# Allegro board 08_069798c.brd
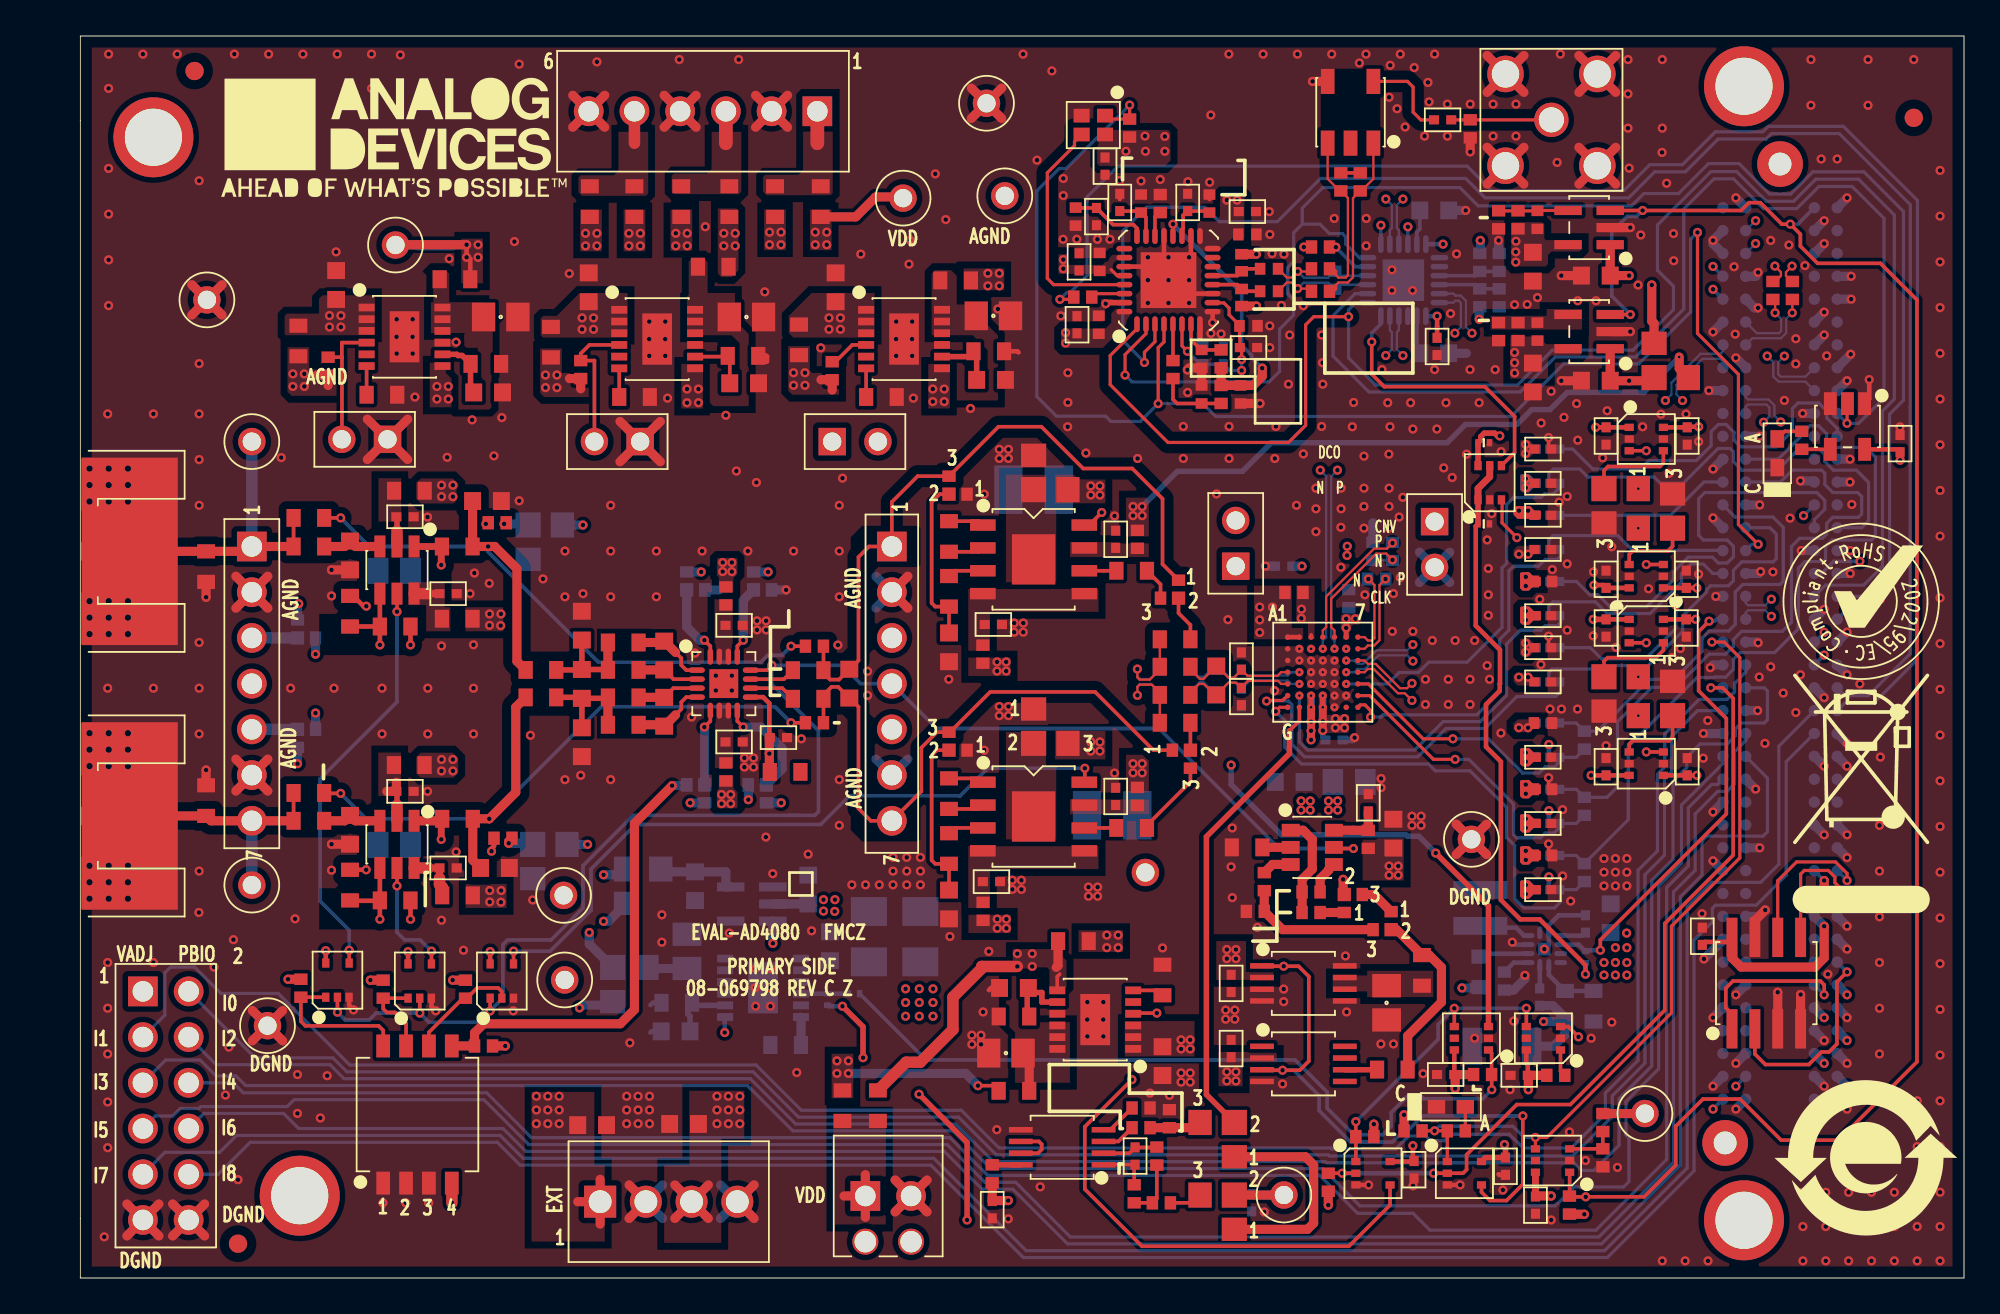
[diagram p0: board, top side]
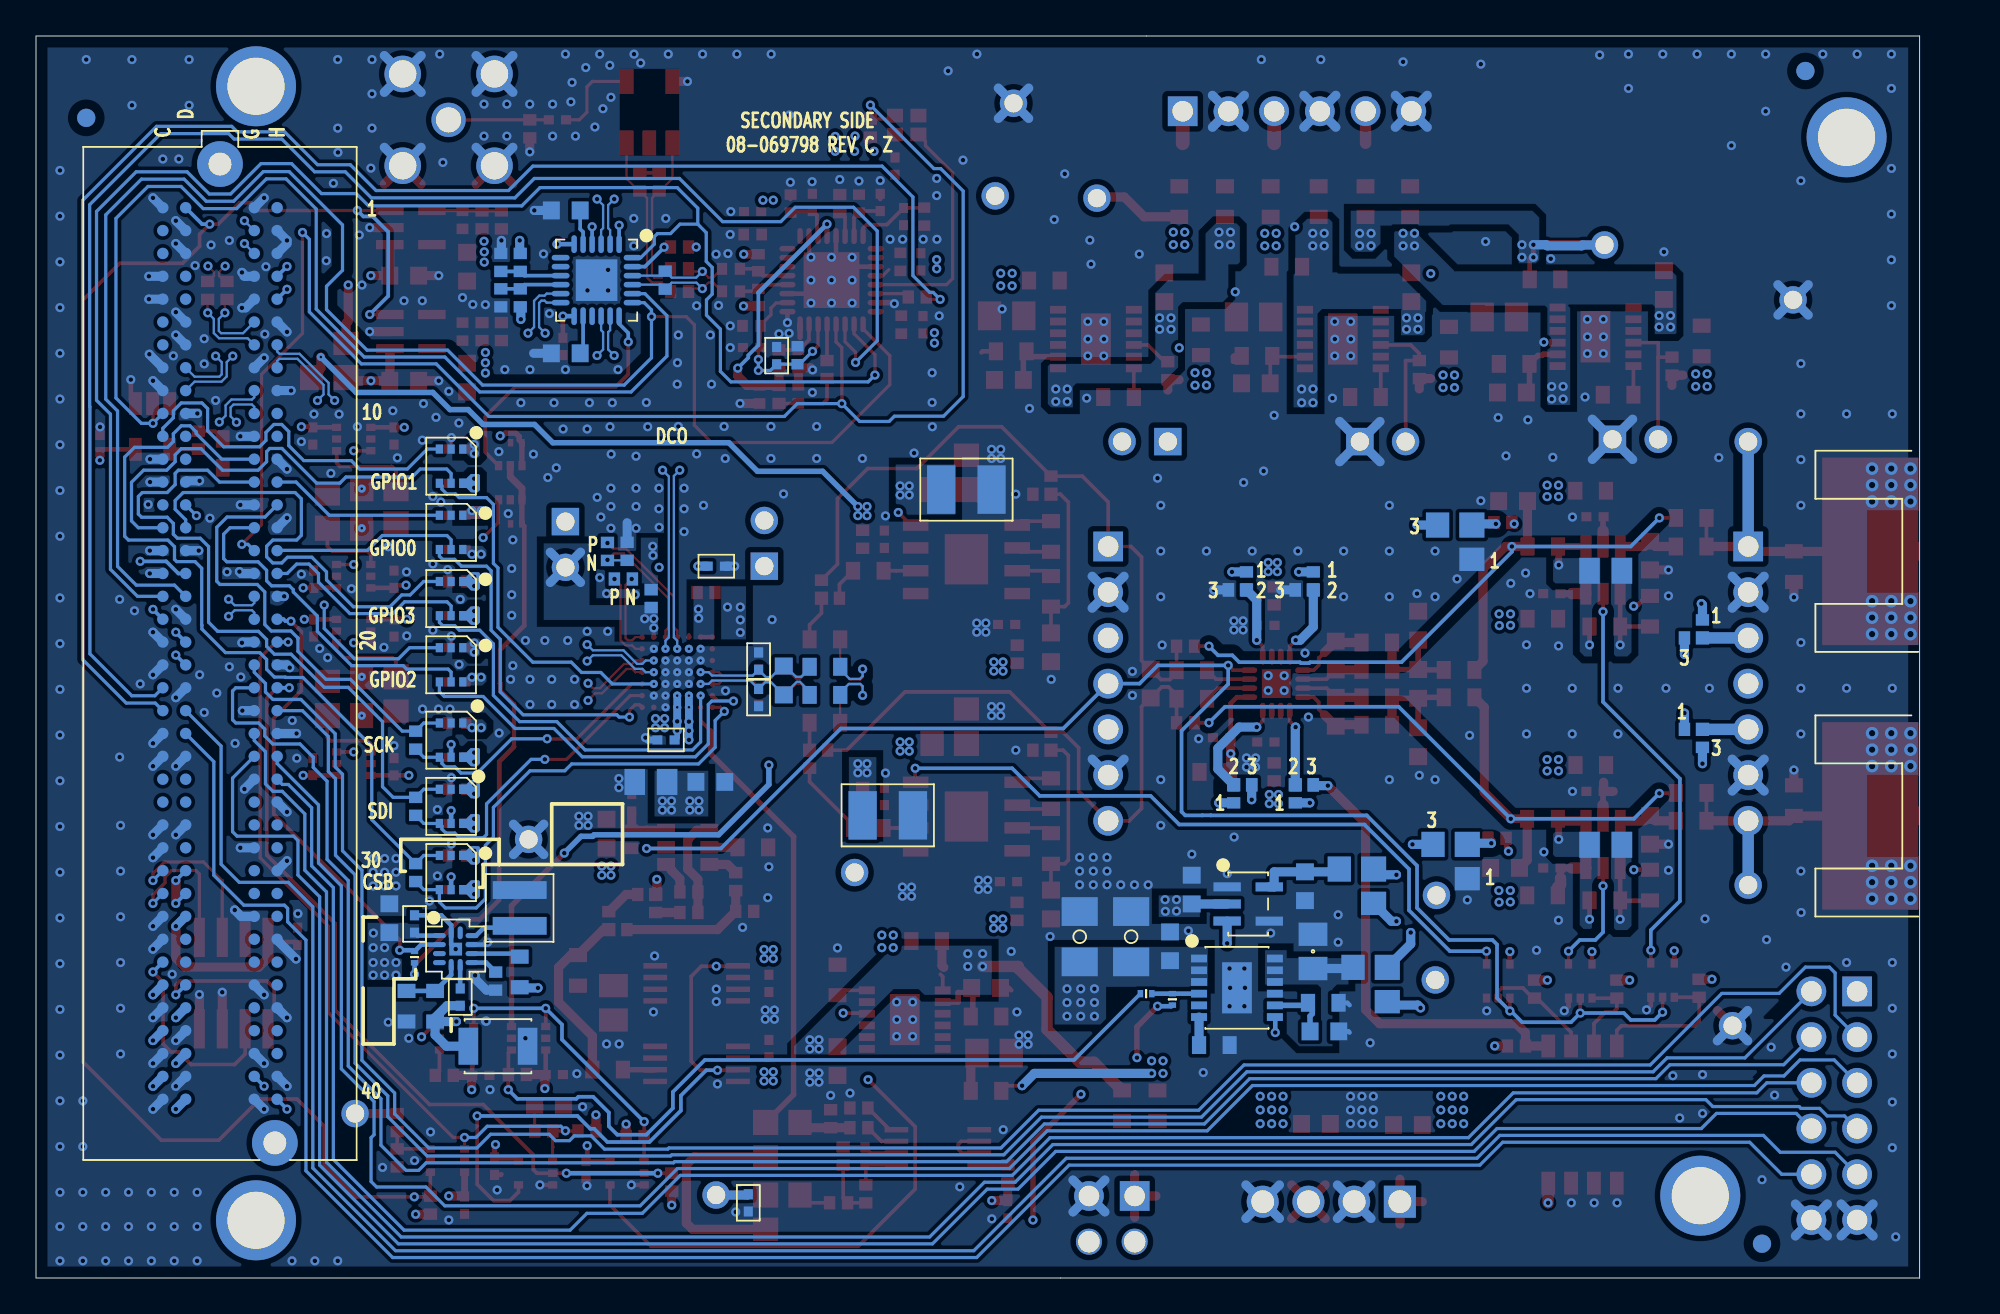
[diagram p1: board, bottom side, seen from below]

Outline 104.64 x 69 mm; copper layers: TOP, L2_GND, L3_PRIMARY_POWER, L4_GND, L5_SECONDARY_POWER, BOTTOM. Coordinates in mm from the lower left corner of the outline.
Outline path: 0,69 104.64,69 104.64,0 0,0 0,69

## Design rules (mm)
constraint set DEFAULT: min track width 0.203
net group CSB: nets CS_N_SRC CSB
net group DIFF_CLK_MATCH: nets CLK_N CLK_P
net group DP4: nets DOC_FMC DOD_FMC
net group DP5: nets DOA_FMC DOB_FMC
net group FDA_ON: nets UNNAMED_8_ADLT6236_I33_ VINP
net group FDA_OP: nets UNNAMED_8_ADLT6236_I15_ VINN
net group FPGACLK: nets FPGACLK_N FPGACLK_P
net group NEG_5V0: nets UNNAMED_12_ADLT8604_I100_FB UNNAMED_12_ADLT8604_I100_RT
net group OSC_EN: nets OSC_EN UNNAMED_7_ADP7118V2_I95_SENSE
net group PG_C2M: nets PG_C2M UNNAMED_12_LINLT3045_I87_EN
net group REFBUF_IN: nets REFBUF_IN UNNAMED_13_ADA48971_I40_
net group UNNAMED_4_CMOSNC7SZ125_I71_Y: nets UNNAMED_4_CMOSNC7SZ125_I71_Y UNNAMED_4_DIOLED_I76_P
net group UNNAMED_8_ADA4899_I108_INV: nets UNNAMED_8_ADA4899_I108_FEEDBACK UNNAMED_8_ADA4899_I108_INV
net group UNNAMED_8_ADA4899_I108_NINV: nets UNNAMED_8_ADA4899_I108_NINV UNNAMED_8_CAP_I93_N1
net group UNNAMED_8_ADA4899_I113_INV: nets UNNAMED_8_ADA4899_I113_FEEDBACK UNNAMED_8_ADA4899_I113_INV
net group UNNAMED_8_ADA4899_I113_NINV: nets UNNAMED_8_ADA4899_I113_NINV UNNAMED_8_CAP_I115_N1
net group UNNAMED_8_RES_I185_N2: nets UNNAMED_8_ADA4899_I108_VOUT UNNAMED_8_RES_I185_N2
net group UNNAMED_8_RES_I186_N2: nets UNNAMED_8_ADA4899_I113_VOUT UNNAMED_8_RES_I186_N2
net group UNNAMED_13_ADA48072_I13_NINV: nets UNNAMED_13_ADA48072_I13_NINV UNNAMED_13_RES_I12_N1
net group VOCM: nets UNNAMED_8_OFFPAGE_I160_A VOCM
net group 5V_SUPP: nets FDA5 PMSEL UNNAMED_8_ADA49451_I81__5 UNNAMED_13_ADA48072_I20_VS VDD_REFBUF VDDAFE_U1 VDDAFE_U2 VDDDRV_A1 VDDDRV_A6
net group +3V3VCCO: nets UNNAMED_7_ADP7118V2_I90_SENSE
net group ADF435X_LOCK: nets ADF435X_LOCK
net group AUXIN+: nets ADCIN+ AUXIN+ IN+ UNNAMED_8_RES_I163_N1
net group AUXIN-: nets ADCIN- AUXIN- IN- UNNAMED_8_RES_I164_N1
net group AVDD11: nets IOVDD
net group CLK_SRCM: nets UNNAMED_7_RES_I8_N1
net group CLK_SRCP: nets UNNAMED_7_RES_I10_N1
net group CNV_N: nets UNNAMED_4_CN160PCDGHV2_I97_LA00NCC
net group CNV_P: nets UNNAMED_4_CN160PCDGHV2_I97_LA00PCC
net group FDA8: nets FDA8
net group MATHCED_DIFFPAIR: nets DA_N DA_P DB_N DB_P DCO_N DCO_P
net group PWRGD: nets PWRGD
net group REF3P: nets REF3P REF3S UNNAMED_13_RES_I29_N2
net group REFBUF_OUT: nets REFBUF_OUT UNNAMED_13_ADA48971_I40__1 UNNAMED_13_ADA48971_I40_OUT
net group SCK: nets SCK
net group SDI: nets SDI
net group SNS33: nets UNNAMED_5_ADM108X_I19_VIN
net group UNNAMED_8_ADLT6236_I15__1: nets UNNAMED_8_ADLT6236_I15__1
net group UNNAMED_8_ADLT6236_I33__1: nets UNNAMED_8_ADLT6236_I33__1
net group UNNAMED_13_ADA48072_I13_INV: nets UNNAMED_13_ADA48072_I13_INV UNNAMED_13_ADA48072_I13_OUT UNNAMED_13_RES_I17_N2 UNNAMED_13_RES_I28_N2
net group VSSAFE: nets UNNAMED_8_ADA49451_I81__4 VSSAFE_U1 VSSAFE_U2 VSSDRV_A1 VSSDRV_A6
net group VTIN: nets CPO FFB UNNAMED_7_ADF435X_I58_SW VTIN

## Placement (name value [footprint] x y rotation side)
A1  ADA4899-1YRDZ  [SO8NB-3-PAD]  52.95 39.93 270 top
A2  ADM1085AKSZ  [SC70-6]  77.27 13.32 90 top
A3  ADM1085AKSZ  [SC70-6]  81.27 13.32 90 top
A4  ADM1085AKSZ  [SC70-6]  81.78 6.53 90 top
A5  ADA4807-2ARMZ  [MSOP8]  54.54 7.26 90 top
A6  ADA4899-1YRDZ  [SO8NB-3-PAD]  52.95 25.64 270 top
C1  0.1uF  [C0402H22]  89.26 46.78 270 top
C2  0.1uF  [C0201]  77.96 41.9 0 top
C3  0.1uF  [C0201]  77.96 46.4 0 top
C4  47uF  [C1206H71]  43.8 18.96 90 bottom
C5  47uF  [C1206H71]  46.66 18.96 90 bottom
C6  10uF  [C0603]  72.94 24.69 90 top
C7  TBD  [C0603_0805]  17.44 39.29 0 bottom
C8  TBD  [C0603_0805]  17.44 24.07 0 bottom
C9  0.1uF  [C0402H22]  71.55 26.4 90 top
C10  4.7uF  [C0603]  60.12 12.05 270 top
C11  4.7uF  [C0603]  28.24 55.04 90 top
C12  4.7uF  [C0603]  41.96 55.04 90 top
C13  4.7uF  [C0603]  14.21 55.17 90 top
C14  22uF  [C0805H60]  51.42 12.49 180 top
C15  56pF  [C0603]  27.86 36.24 270 top
C16  56pF  [C0603]  27.86 29.77 270 top
C17  82pF  [C0603]  32.44 34.58 90 top
C18  82pF  [C0603]  32.44 31.46 270 top
C19  0.1uF  [C0402H22]  36.32 36.26 0 top
C20  0.1uF  [C0402H22]  36.32 29.78 0 top
C21  22uF  [C0805H60]  37 53.39 0 top
C22  22uF  [C0805H60]  50.72 53.45 0 top
C23  22uF  [C0805H60]  23.35 53.39 0 top
C24  1uF  [C0603]  85.01 19.99 90 bottom
C25  4.7uF  [C0603]  41.64 18.43 90 bottom
C26  0.1uF  [C0402H22]  83.61 19.67 90 bottom
C27  0.1uF  [C0402H22]  81.07 15.61 270 bottom
C28  22uF  [C0805H60]  33.7 18.15 90 bottom
C29  22uF  [C1210H106]  78.98 12.88 0 bottom
C30  47uF  [C0805H60]  72.56 15.29 270 top
C31  8200pF  [C0603]  22.59 43.17 180 top
C32  8200pF  [C0603]  23.03 22.78 0 top
C33  0.1uF  [C0402H22]  38.78 30.02 0 top
C34  10uF  [C0603]  33.54 8.56 180 top
C35  27pF  [C0603]  63.1 33.2 90 top
C36  82pF  [C0402H22]  64.5 34.28 270 top
C37  82pF  [C0402H22]  64.5 32.31 270 top
C38  10pF  [C0603]  63.1 33.2 90 bottom
C39  82pF  [C0402H22]  64.5 34.28 270 bottom
C40  82pF  [C0402H22]  64.5 32.24 270 bottom
C41  TBD0805  [C0805]  70.48 27.56 0 bottom
C42  22uF  [C0603]  67.18 27.56 180 bottom
C43  0.1uF  [C0402H22]  69.64 29.89 0 bottom
C44  0.1uF  [C0402H22]  80.83 4.05 270 top
C45  0.01uF  [C0603]  50.59 49.9 0 top
C46  0.01uF  [C0603]  51.86 16.11 180 top
C47  0.1uF  [C0402H22]  75.85 11.3 180 top
C48  0.1uF  [C0402H22]  79.93 11.26 180 top
C49  10UF  [C0402]  81.25 23.47 0 top
C50  10UF  [C0402]  81.25 27.15 0 top
C51  10UF  [C0402]  81.25 30.83 0 top
C52  0.1uF  [C0402H22]  81.25 21.58 0 top
C53  0.1uF  [C0402H22]  81.25 25.25 0 top
C54  0.1uF  [C0402H22]  81.25 28.93 0 top
C55  0.1uF  [C0402H22]  79.17 6.21 270 top
C56  0.1uF  [C0402H22]  74.09 6.02 270 top
C57  0.1uF  [C0402H22]  63.93 12.75 90 top
C58  0.1uF  [C0402H22]  63.93 16.37 270 top
C59  0.1uF  [C0402H22]  89.21 36.11 270 top
C60  0.1uF  [C0402H22]  58.59 6.77 270 top
C61  0.1uF  [C0402H22]  50.66 3.8 270 top
C62  0.1uF  [C0402H22]  81.25 42.37 0 top
C63  0.1uF  [C0402H22]  101.09 46.36 90 top
C64  0.1uF  [C0402H22]  90.1 18.99 90 top
C65  0.1uF  [C0402H22]  75.67 64.34 180 top
C66  0.1uF  [C0402H22]  63.49 51.24 90 bottom
C67  15pF  [C0603]  14.98 40.14 270 top
C68  0.1uF  [C0402H22]  81.25 46.05 0 top
C69  0.47uF  [C0603]  75.21 51.37 0 bottom
C70  0.47uF  [C0603]  75.21 59.31 0 bottom
C71  0.1uF  [C0402H22]  81.25 35.02 0 top
C72  0.1uF  [C0402H22]  75.37 51.75 270 top
C73  10UF  [C0402]  81.25 38.69 0 top
C74  0.1uF  [C0402H22]  81.25 40.47 0 top
C75  1000PF  [C0603]  42.72 33.02 270 top
C76  0.1uF  [C0402H22]  81.25 44.15 0 top
C77  0.1uF  [C0402H22]  81.25 33.12 0 top
C78  0.1uF  [C0402H22]  81.25 36.79 0 top
C79  15pF  [C0603]  14.98 24.9 270 top
C80  0.1uF  [C0402H22]  84.75 36.11 270 top
C81  0.1uF  [C0402H22]  89.26 28.4 90 top
C82  0.1uF  [C0402H22]  84.75 46.78 270 top
C83  0.1uF  [C0402H22]  89.21 38.82 90 top
C84  0.1uF  [C0402H22]  84.75 28.4 90 top
C85  0.1uF  [C0402H22]  84.75 38.82 90 top
C86  0.01uF  [C0603]  36.88 49.71 0 top
C87  0.01uF  [C0603]  22.65 49.2 0 top
C88  0.1uF  [C0402H22]  20.43 38.02 0 top
C89  0.1uF  [C0402H22]  18.03 42.29 180 top
C90  0.1uF  [C0402H22]  20.43 22.78 0 top
C91  0.1uF  [C0402H22]  18.03 27.04 180 top
C92  22pF  [C0603]  48.25 20.75 270 top
C93  47uF  [C1210H95]  57.32 25.7 180 bottom
C94  47uF  [C1210H95]  52.95 43.8 0 bottom
C95  0.1uF  [C0402H22]  57.51 41.04 90 top
C96  0.1uF  [C0402H22]  50.72 36.31 180 top
C97  0.1uF  [C0402H22]  57.51 26.75 90 top
C98  0.1uF  [C0402H22]  50.61 22.02 180 top
C99  0.1uF  [C0402H22]  66.85 39.55 180 bottom
C100  0.1uF  [C0402H22]  65.07 4.18 90 bottom
C101  10uF  [C0603]  28.43 8.49 0 top
C102  0.01uF  [C0603]  33.07 13.7 180 bottom
C103  27PF  [C0603]  27.86 33.01 270 top
C104  1uF  [C0402]  80.94 58.79 270 top
C105  1uF  [C0402]  80.94 52.58 270 top
C109  22pF  [C0603]  48.25 35.04 270 top
C118  4.7uF  [C0603]  40.44 21.58 90 bottom
C119  4.7uF  [C0603]  34.15 21.77 270 bottom
C120  2000pF  [C0402]  64.45 49.09 270 top
C121  0.1uF  [C0402H22]  57.74 59.75 90 top
C122  0.027uF  [C0402]  62.29 49.09 90 top
C123  10pF  [C0402]  58.92 59.69 90 top
C124  0.1uF  [C0402H22]  55.37 52.96 90 top
C125  390pF  [C0402]  62.29 51.06 270 top
C126  10pF  [C0402]  64.89 52.9 0 top
C127  0.1uF  [C0402H22]  56.45 58.97 270 top
C128  0.1uF  [C0402H22]  64.89 51.69 0 top
C129  10pF  [C0402]  55.29 58.97 270 top
C130  10pF  [C0402]  56.57 52.96 90 top
C131  0.1uF  [C0402H22]  56.92 61.77 270 top
C132  10pF  [C0402]  62.34 51.27 90 bottom
C133  0.1uF  [C0402H22]  55.48 56.45 90 top
C134  10pF  [C0402]  56.62 56.45 90 top
C135  0.1uF  [C0402H22]  64.83 59.25 0 top
C136  0.1uF  [C0402H22]  61.51 59.75 90 top
C137  1000pF  [C0402]  66.03 54.82 0 top
C138  1000pF  [C0402]  66.03 56.07 0 top
C139  10pF  [C0402]  64.83 57.98 0 top
C140  10pF  [C0402]  62.72 59.69 90 top
C141  2.2uF  [C0603]  84.18 55.69 180 top
C142  2.2uF  [C0603]  84.18 49.85 180 top
C143  2.2uF  [C0603]  80.69 56.18 270 top
C144  2.2uF  [C0603]  80.69 50.02 270 top
CLKIN  1-1478979-0  [CNTYCO78974]  81.72 64.34 90 top
CNVEN  APT1608LVBC/D  [LED0603]  94.27 45.82 90 top
DS1  APT1608LZGCK  [LED0603]  76.14 9.51 0 top
INM  142-0701-851  [CNSMA10G62THK_EDGE]  0 25.67 180 top
INP  142-0701-851  [CNSMA10G62THK_EDGE]  0 40.37 180 top
IOVDD  RED  [CNKEY5001TP]  45.7 59.99 0 top
JP1  0  [3PINJUMPER_0402]  72.82 19.35 0 top
JP2  0  [3PINJUMPER_0402]  70.21 21.31 180 top
JP3  3PIN_JUMPER  [3PINJUMPER_0402]  33.68 38.23 180 bottom
JP4  3PIN_JUMPER  [3PINJUMPER_0402]  34.68 27.4 0 bottom
JP5  3PIN_JUMPER  [3PINJUMPER_0402]  37.4 38.23 180 bottom
JP6  3PIN_JUMPER  [3PINJUMPER_0402]  38.11 27.4 0 bottom
JP7  0  [3PINJUMPER_0603]  24.87 40.88 90 bottom
JP8  0  [3PINJUMPER_0603]  64.1 7.69 90 top
JP9  0  [3PINJUMPER_0603]  64.1 3.66 90 top
JP10  0  [3PINJUMPER_0603]  85.59 33.4 180 top
JP11  0  [3PINJUMPER_0603]  87.5 31.24 0 top
JP12  0  [3PINJUMPER_0603]  85.59 43.85 180 top
JP13  0  [3PINJUMPER_0603]  87.5 41.66 0 top
JP14  0  [3PINJUMPER_0603]  25.13 23.14 90 bottom
JP15  0  [3PINJUMPER_0402]  48.25 43.55 270 top
JP16  0  [3PINJUMPER_0402]  48.25 29.32 270 top
JP17  0  [3PINJUMPER_0402]  61.01 37.77 0 top
JP18  0  [3PINJUMPER_0402]  61.67 29.32 90 top
JP19  3PIN_JUMPER  [3PINJUMPER_0402]  12.06 35.56 180 bottom
JP20  3PIN_JUMPER  [3PINJUMPER_0402]  12.06 30.48 90 bottom
JP21  0  [3PINJUMPER_0603]  52.95 44.75 270 top
JP22  0  [3PINJUMPER_0603]  52.95 30.66 270 top
JP23  0  [3PINJUMPER_0603]  87.42 50.98 270 top
JP24  0  [3PINJUMPER_0603]  29.57 16.3 90 bottom
JP25  0  [3PINJUMPER_0603]  30.34 21.77 90 bottom
L1  47UH  [LSMSQ118H59_39X118]  77.77 20.56 90 bottom
L3  100nH  [L0402]  64.51 54.47 270 top
L4  100nH  [L0402]  64.51 56.4 90 top
NOREF  -  [unnamed]  8.76 1.91 0 top
NOREF#2  -  [unnamed]  6.34 67.06 0 top
NOREF#3  -  [unnamed]  92.42 3.2 0 top
NOREF#4  -  [#2]  42.6 -81.98 0 top
NOREF#5  -  [#2]  -130.37 -241.3 0 top
NOREF#6  -  [#2]  272.22 127.42 180 top
NOREF#7  -  [#2]  152.01 16.95 0 top
NOREF#8  -  [#2]  115.31 28.58 0 top
NOREF#9  -  [#2]  0.38 -9.14 270 top
NOREF#10  -  [#2]  99.18 6.68 0 top
NOREF#11  -  [#2]  0 0 0 top
NOREF#12  -  [#2]  0 69 0 top
NOREF#13  -  [#2]  104.64 0 0 top
NOREF#14  -  [#2]  33.95 -146.13 0 top
NOREF#15  -  [#2]  -4.32 1.02 0 top
NOREF#16  -  [unnamed]  101.85 64.45 0 top
NOREF#17  -  [#2]  0 69 0 top
NOREF#18  -  [unnamed]  92.42 66.21 0 top
NOREF#19  -  [#2]  -130.37 -241.3 0 top
NOREF#20  -  [#2]  -86.14 -57.15 0 top
NOREF#21  -  [#2]  3.47 3.22 0 top
NOREF#22  -  [#2]  71.61 31.16 0 top
NOREF#23  -  [#2]  -69.41 129.54 0 top
NOREF#24  -  [#2]  98.93 37.59 0 top
NOREF#25  -  [#2]  156.77 53.53 0 top
NOREF#26  -  [#2]  -130.37 -241.3 0 top
NOREF#27  -  [#2]  -9.32 39.65 0 top
NOREF#28  -  [#2]  3.47 3.22 0 top
NOREF#29  -  [unnamed]  12.19 4.57 0 top
NOREF#30  -  [#2]  104.64 0 90 top
NOREF#31  -  [#2]  10.73 2.9 0 top
NOREF#32  -  [#2]  17.44 63.89 0 top
NOREF#33  -  [unnamed]  4.06 63.37 0 top
NOREF#34  -  [#2]  108.2 37.16 0 top
NOREF#35  -  [#2]  -130.37 -241.3 0 top
NOREF#36  -  [#2]  60.45 149.19 0 top
NOREF#37  -  [#2]  0 0 0 top
NOREF#38  -  [unnamed]  101.85 64.45 180 bottom
NOREF#39  -  [unnamed]  6.34 67.06 180 bottom
NOREF#40  -  [unnamed]  8.76 1.91 180 bottom
P1  TSW-107-14-G-S  [CNTHMHDR1X7L700W100H433]  9.53 33.02 270 top
P2  SSW-107-01-T-S  [CNRCPT1X7H335LD35]  45.08 40.64 270 top
P3  ASP-134604-01  [CNSAMTECASP-134604-01]  94.42 34.7 270 bottom
P4  1725698  [CN1X6H335]  40.94 64.82 180 top
P5  69157-102HLF  [CNBERG69157-102]  17.06 46.59 180 top
P6  69157-102HLF  [CNBERG69157-102]  41.77 46.47 0 top
P7  TSW-106-07-F-D  [CNHDR2X6H330]  3.47 15.92 270 top
P8  1725672  [CNPHOENIX1725672]  28.87 4.24 0 top
P9  69157-102HLF  [CNBERG69157-102]  64.18 39.55 90 top
P10  69157-102HLF  [CNBERG69157-102]  75.23 42.02 270 top
P11  1725656  [CNTH1X2H335]  43.61 4.56 0 top
P12  69157-102HLF  [CNBERG69157-102]  31.1 46.47 180 top
R1  0  [R0402]  71.55 24.37 270 top
R2  49.9  [R0603]  6.98 39.52 270 top
R3  49.9  [R0603]  6.98 26.52 90 top
R4  0  [R0603]  12.69 40.64 0 top
R5  499  [R0603]  14.98 37.04 270 top
R6  0  [R0603]  12.69 25.4 0 top
R7  499  [R0603]  14.98 21.83 270 top
R8  499  [R0603]  17.49 36.2 0 top
R9  499  [R0603]  17.49 20.98 0 top
R10  300  [R0603]  25.59 33.78 0 top
R11  300  [R0603]  25.59 32.26 0 top
R12  0  [R0603]  30.16 33.78 0 top
R13  0  [R0603]  30.16 32.26 0 top
R14  300  [R0603]  30.16 35.31 0 top
R15  300  [R0603]  30.16 30.73 0 top
R16  10K  [R0402]  69.32 5.32 90 top
R17  0  [R0603]  48.25 41.2 90 top
R18  0  [R0402]  40.78 30.85 0 top
R19  100K  [R0402]  27.8 50.47 90 top
R20  100K  [R0402]  13.76 50.66 90 top
R21  0  [R0603]  35.16 56.18 0 top
R22  0  [R0603]  48.62 55.42 0 top
R23  0  [R0603]  20.81 55.48 0 top
R24  0  [R0201]  42.97 15.8 180 bottom
R26  0  [R0603]  18.28 43.74 0 top
R27  0  [R0603]  18.27 28.5 0 top
R28  0  [R0603]  20.95 21.26 0 top
R29  0  [R0402]  23.16 41.96 180 top
R30  0  [R0603]  39.15 28.12 0 top
R31  68  [R0603]  60.82 33.96 0 bottom
R32  20  [R0603]  60.82 33.96 0 top
R33  0  [R0402]  40.78 35.1 0 top
R34  0  [R0603]  44.31 9.57 90 top
R35  100K  [R0402]  41.77 50.4 90 top
R36  0  [R0402]  67.42 38.09 0 top
R37  0  [R0402]  70.47 37.74 270 bottom
R38  0  [R0402]  71.8 40.37 270 bottom
R39  0  [R0402]  94.03 54.86 270 top
R40  0  [R0402]  95.11 54.86 270 top
R41  35.7K  [R0402]  84.58 8.64 270 top
R42  10K  [R0402]  84.58 6.68 270 top
R43  10K  [R0402]  82.72 4.05 90 top
R44  10K  [R0402]  77.9 11.3 0 top
R45  10K  [R0402]  81.96 11.26 0 top
R46  1.5K  [R0402]  74.03 8.18 0 top
R47  10K  [R0402]  71.36 7.86 180 top
R48  10  [R0402]  58.92 8.35 180 top
R49  10  [R0402]  59.8 6.77 270 top
R50  0  [R0402]  58.54 4.68 270 top
R51  0  [R0402]  50.66 5.79 270 top
R52  0  [R0603]  12.69 42.23 0 top
R53  100K  [R0402]  12.25 16.1 270 top
R54  100K  [R0402]  22.4 12.89 0 top
R55  100K  [R0402]  16.82 16.05 270 top
R56  100K  [R0402]  21.39 16.05 270 top
R57  0  [R0603]  48.25 26.91 90 top
R58  25  [R0603]  48.25 38.15 90 top
R59  25  [R0603]  48.25 23.86 90 top
R60  1.1K  [R0402]  95.63 46.54 90 top
R61  100K  [R0402]  58.29 63.89 90 top
R62  100  [R0402]  77.21 63.84 270 top
R63  49.9  [R0402]  71.1 60.9 90 top
R64  49.9  [R0402]  70.02 60.9 270 top
R65  0  [R0402]  68.89 54.82 180 top
R66  0  [R0603]  20.94 40.64 0 top
R67  0  [R0402]  58.92 9.45 180 top
R68  0  [R0402]  68.89 56.07 180 top
R69  100  [R0402]  69.69 55.44 270 bottom
R70  0  [R0603]  60.82 35.48 180 top
R71  100K  [R0402]  68.89 57.28 0 top
R72  100K  [R0402]  77.74 56.42 270 bottom
R73  100K  [R0402]  78.82 56.42 90 bottom
R74  100K  [R0402]  77.74 54.45 90 bottom
R75  100K  [R0402]  78.82 54.45 270 bottom
R76  0  [R0603]  60.82 30.85 180 top
R77  100K  [R0201]  41.51 15.48 90 bottom
R78  0  [R0402]  23.48 24.43 0 top
R79  0  [R0603]  38.59 59.8 270 top
R80  0  [R0603]  33.38 59.8 270 top
R81  0  [R0603]  28.3 59.8 270 top
R82  0  [R0603]  42.34 9.57 90 top
R83  0  [R0603]  41.13 59.8 270 top
R84  0  [R0603]  36.05 59.8 270 top
R85  1.1K  [R0402]  76.44 8.18 0 top
R86  10K  [R0402]  60.5 8.85 90 top
R87  0  [R0402]  60.05 4.18 0 top
R88  20  [R0603]  60.82 32.4 0 top
R89  68  [R0603]  60.82 32.4 0 bottom
R90  0  [R0603]  30.78 59.8 270 top
R91  0  [R0603]  55.16 18.72 180 top
R92  0  [R0603]  26.14 51.99 90 top
R93  0  [R0603]  12.11 52.06 90 top
R94  0  [R0603]  39.92 52.12 90 top
R95  33K  [R0603]  51.86 14.53 180 top
R96  20K  [R0603]  36.81 51.23 0 top
R97  11K  [R0603]  50.46 51.48 0 top
R98  0  [R0402]  79.87 58.79 270 top
R99  10K  [R0402]  78.79 58.79 90 top
R100  0  [R0402]  79.87 52.58 270 top
R101  10K  [R0402]  78.79 52.58 90 top
R102  56  [R0603]  40.43 33.77 0 top
R103  56  [R0603]  40.43 32.18 0 top
R104  5.6  [R0603]  58.4 25 0 top
R105  5.6  [R0603]  58.4 39.29 0 top
R106  0  [R0603]  12.69 26.95 0 top
R107  11K  [R0603]  22.52 50.79 0 top
R108  3K  [R0603]  60.12 16.56 90 top
R109  0  [R0402]  83.55 22.52 270 bottom
R110  0  [R0402]  83.55 26.2 270 bottom
R111  0  [R0402]  83.55 29.88 270 bottom
R112  3K  [R0603]  30.79 48.94 0 top
R113  0  [R0603]  20.94 36.62 0 top
R114  0  [R0603]  20.95 25.51 0 top
R115  0  [R0402]  35.86 37.89 90 top
R116  0  [R0402]  35.86 28.12 270 top
R117  0  [R0402]  58.72 41.04 270 top
R118  0  [R0402]  58.72 26.75 270 top
R119  316  [R0402]  63.37 49.09 270 top
R120  845  [R0402]  63.37 51.06 90 top
R121  5.1K  [R0402]  59.99 59.69 90 top
R122  0  [R0402]  60.7 50.47 90 top
R123  0  [R0402]  55.68 54.5 180 top
R124  0  [R0402]  34.18 38.23 0 bottom
R125  0  [R0402]  34.18 27.4 180 bottom
R126  0  [R0402]  37.9 38.23 0 bottom
R127  0  [R0402]  37.61 27.4 180 bottom
R128  0  [R0402]  50.13 34.66 90 top
R129  0  [R0402]  50.15 20.37 90 top
R130  3K  [R0603]  44.5 48.94 0 top
R131  3K  [R0603]  16.75 49.07 0 top
R132  0  [R0603]  51.86 10.4 180 top
R133  100K  [R0201]  83.61 17.83 90 bottom
R134  50K  [R0603]  33.13 15.29 180 bottom
R135  500  [R0603]  39.18 12.94 180 bottom
R136  0  [R0402]  79.1 16.5 270 bottom
R137  18.2K  [R0603]  77.77 17 270 bottom
R138  187K  [R0603]  82.47 15.1 270 bottom
R139  1MEG  [R0603]  84.06 15.1 270 bottom
R146  0  [R0603]  72.88 11.58 0 top
R147  0  [R0603]  74.53 17.09 90 top
R148  10K  [R0402]  65.27 20.37 180 top
R149  0  [R0402]  65.77 22.02 90 top
R150  0  [R0402]  68.37 21.45 180 top
R151  0  [R0402]  68.37 20.31 0 top
R152  0  [R0603]  64.82 23.92 180 top
REF  RED  [CNKEY5001TP]  59.16 22.53 0 top
RTCLK  100  [R0402]  72.01 38.83 0 bottom
RTCNV  100  [R0402]  72.89 40.36 270 bottom
S1  218-4LPST  [SWSML246W228H104]  18.73 9.08 0 top
T1  MABA-007159-000000  [ETC1]  70.56 64.76 180 top
TINM  RED  [CNKEY5001TP]  9.53 21.83 0 top
TINP  RED  [CNKEY5001TP]  9.53 46.47 0 top
TP1  BLK  [CNKEY5001TP]  77.27 24.37 0 top
TP2  BLK  [CNKEY5001TP]  7.03 54.34 0 top
TP3  BLK  [CNKEY5001TP]  50.34 65.26 0 top
TP4  BLK  [CNKEY5001TP]  10.4 14.02 0 top
U1  LT6236HS6#TRMPBF  [TSOT23_6]  17.59 39.33 180 top
U2  LT6236HS6#TRMPBF  [TSOT23_6]  17.59 24.09 180 top
U3  ADA4945-1ACPZ-R7  [QFN16_3X3_PAD1_6X1_6]  35.75 33.02 270 top
U4  SN74AVC1T45DCKR  [SC70-6]  86.99 35.94 270 top
U5  SN74AVC1T45DCKR  [SC70-6]  86.99 28.58 90 top
U6  SN74AVC1T45DCKR  [SC70-6]  86.99 46.61 270 top
U7  SN74AVC1T45DCKR  [SC70-6]  86.99 38.99 90 top
U8  AD4080  [BGA49_5X5]  69.02 33.66 270 top
U9  SN74AVC1T45DCKR  [SC70-6]  78.29 44.18 0 top
U11  SN74AVC1T45DCKR  [SC70-6]  81.58 22.52 0 bottom
U12  SN74AVC1T45DCKR  [SC70-6]  81.58 26.2 0 bottom
U13  SN74AVC1T45DCKR  [SC70-6]  81.58 29.88 0 bottom
U14  SN74AVC1T45DCKR  [SC70-6]  81.58 41.42 0 bottom
U15  SN74AVC1T45DCKR  [SC70-6]  81.58 45.1 0 bottom
U16  SN74AVC1T45DCKR  [SC70-6]  81.58 34.07 0 bottom
U17  SN74AVC1T45DCKR  [SC70-6]  81.58 37.74 0 bottom
U18  M24C02-RMN6TP  [SO8]  93.66 16.38 0 top
U19  ADP7182AUJZ-2.5  [TSOT-5]  37.3 20.78 270 bottom
U20  AD9508BCPZ  [QFN24_4X4_PAD2_3X2_3]  73.5 55.44 0 bottom
U21  LT3045EMSE#PBF  [MSOP12_PAD2_845X1_651]  56.38 14.36 90 top
U23  TC7S08FU,LF  [SC70-5_A]  76.89 5.82 270 top
U24  TC7S08FU,LF  [SC70-5_A]  71.81 5.82 270 top
U25  LTC6655BHMS8-3#PBF  [MSOP8]  67.94 16.37 270 top
U26  SN74LVC1G00DCKT  [SC70-5]  14.28 16.55 0 top
U27  SN74LVC1G00DCKT  [SC70-5]  18.85 16.5 0 top
U28  TC7S08FU,LF  [SC70-5_A]  23.41 16.5 0 top
U29  NC7SZ125M5X  [SOT23-M12]  98.17 47.31 180 top
U30  ADF4350BCPZ  [QFN32_5X5_PAD3_1X3_1]  60.45 55.44 0 top
U31  ADP7118AUJZ-3.3  [TSOT-5]  83.81 58.36 90 top
U32  ADP7118AUJZ-3.3  [TSOT-5]  83.81 52.58 90 top
U33  LT3045EMSE#PBF  [MSOP12_PAD2_845X1_651]  32.04 52.16 270 top
U34  LT3045EMSE#PBF  [MSOP12_PAD2_845X1_651]  45.76 52.16 270 top
U35  LT3045EMSE#PBF  [MSOP12_PAD2_845X1_651]  18.01 52.29 270 top
U36  LT6657BHMS8-3#PBF  [MSOP8]  67.94 11.9 270 top
U37  LT3045EMSE#PBF  [MSOP12_PAD2_845X1_651]  37.92 16.12 270 bottom
U38  LT8604CAV#TRMPBF  [QFN12_2X2_PAD0_7X0_7]  81.33 18.27 270 bottom
U39  ADA4897-1ARJZ  [SOT23_6-2]  68.44 23.92 270 top
UNK5V_VDD  RED  [CNKEY5001TP]  26.84 21.26 0 top
VDD33  RED  [CNKEY5001TP]  86.91 9.14 0 top
VDD_11  RED  [CNKEY5001TP]  17.51 57.39 0 top
VDDLDO  RED  [CNKEY5001TP]  51.35 60.12 0 top
VOCM  RED  [CNKEY5001TP]  66.86 4.61 180 top
VSS2V5  RED  [CNKEY5001TP]  26.91 16.56 0 top
Y1  25MEGHZ  [YSML79W63H31_A]  56.27 64.05 180 top

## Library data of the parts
A1 A6 = ADA4899: Tolerance: N/A; User Part Number: UPN; alternate symbols: (SO8NB-3-PAD); part number: ADA4899_SM-ADA4899-1YRDZ,E005983,SO8NB-3-PAD; tolerance: N/A
A2-A4 = ADM108X: Tolerance: N/A; User Part Number: UPN; alternate symbols: (SC70-6); part number: ADM108X_SM-ADM1085AKSZ,E014794,SC70-6; tolerance: N/A
A5 = ADA4807_2: Tolerance: N/A; User Part Number: UPN; alternate symbols: (MSOP8); part number: ADA4807_2_SM-ADA4807-2ARMZ,E025561,MSOP8; tolerance: N/A
C1 C9 C19 C20 C26 C27 C33 C43 C44 C47 C48 C52-C66 C68 C71 C72 C74 C76-C78 C80-C85 C88-C91 C95-C100 C121 C124 C127 C128 C131 C133 C135 C136 = CAP: Tolerance: 10; User Part Number: UPN; alternate symbols: (C0402H22); part number: CAP_SM-0.1UF,50V,10,E018452,C0402H22; tolerance: 10
C2 C3 = CAP: Tolerance: 10; User Part Number: UPN; alternate symbols: (C0201); part number: CAP_SM-0.1UF,25V,10,E022721,C0201; tolerance: 10
C4 C5 = CAP: Tolerance: 20; User Part Number: UPN; alternate symbols: (C1206H71); part number: CAP_SM-47UF,16V,20,E033215,C1206H71; tolerance: 20
C6 C34 C101 = CAP: User Part Number: UPN; Tolerance: 10; alternate symbols: (C0603); part number: CAP_SM-10UF,25V,10,E030977,C0603; tolerance: 10
C7 C8 = CAP: User Part Number: UPN; Tolerance: N/A; alternate symbols: (C0603_0805); part number: CAP_SM-TBD,N/A,N/A,E029810,C0603_0805; tolerance: N/A
C10-C13 C25 = CAP: User Part Number: UPN; Tolerance: 10; alternate symbols: (C0603); part number: CAP_SM-4.7UF,16V,10,E020112,C0603; tolerance: 10
C14 C21-C23 C28 = CAP: Tolerance: 20; User Part Number: UPN; alternate symbols: (C0805H60); part number: CAP_SM-22UF,25V,20,E032575,C0805H60; tolerance: 20
C15 C16 = CAP: User Part Number: UPN; Tolerance: 5; alternate symbols: (C0603); part number: CAP_SM-56PF,50V,5,E000413,C0603; tolerance: 5
C17 C18 = CAP: User Part Number: UPN; Tolerance: 5; alternate symbols: (C0603); part number: CAP_SM-82PF,50V,5,E000414,C0603; tolerance: 5
C24 = CAP: User Part Number: UPN; Tolerance: 10; alternate symbols: (C0603); part number: CAP_SM-1UF,50V,10,E023087,C0603; tolerance: 10
C29 = CAP: Tolerance: 20; User Part Number: UPN; alternate symbols: (C1210H106); part number: CAP_SM-22UF,16V,20,E034214,C1210H106; tolerance: 20
C30 = CAP: Tolerance: 20; User Part Number: UPN; alternate symbols: (C0805H60); part number: CAP_SM-47UF,6.3V,20,E025498,C0805H60; tolerance: 20
C31 C32 = CAP: User Part Number: UPN; Tolerance: 5; alternate symbols: (C0603); part number: CAP_SM-8200PF,25V,5,E024853,C0603; tolerance: 5
C35 = CAP: User Part Number: UPN; Tolerance: 5; alternate symbols: (C0603); part number: CAP_SM-27PF,50V,5,E000395,C0603; tolerance: 5
C36 C37 C39 C40 = CAP: Tolerance: 5; User Part Number: UPN; alternate symbols: (C0402H22); part number: CAP_SM-82PF,50V,5,E026785,C0402H22; tolerance: 5
C38 = CAP: User Part Number: UPN; Tolerance: 0.5pF; alternate symbols: (C0603); part number: CAP_SM-10PF,50V,0.5PF,E016319,C0603; tolerance: 0.5pF
C41 = CAP: User Part Number: UPN; alternate symbols: (C0805); part number: CAP_SM-TBD0805,TBD0805,TBD0805,E000383,C0805
C42 = CAP: User Part Number: UPN; Tolerance: 20; alternate symbols: (C0603); part number: CAP_SM-22UF,6.3V,20,E021512,C0603; tolerance: 20
C45 C46 C86 C87 C102 = CAP: User Part Number: UPN; Tolerance: 10; alternate symbols: (C0603); part number: CAP_SM-0.01UF,200V,10,E031666,C0603; tolerance: 10
C49-C51 C73 = CAP: User Part Number: UPN; Tolerance: 20; alternate symbols: (C0402); part number: CAP_SM-10UF,10V,20,E061569,C0402; tolerance: 20
C67 C79 = CAP: User Part Number: UPN; Tolerance: 5; alternate symbols: (C0603); part number: CAP_SM-15PF,50V,5,E000409,C0603; tolerance: 5
C69 C70 = CAP: User Part Number: UPN; Tolerance: 10; alternate symbols: (C0603); part number: CAP_SM-0.47UF,16V,10,E012085,C0603; tolerance: 10
C75 = CAP: User Part Number: UPN; Tolerance: 1; alternate symbols: (C0603); part number: CAP_SM-1000PF,100V,1,E055828,C0603; tolerance: 1
C92 C109 = CAP: User Part Number: UPN; Tolerance: 5; alternate symbols: (C0603); part number: CAP_SM-22PF,50V,5,E000411,C0603; tolerance: 5
C93 C94 = CAP: Tolerance: 10; User Part Number: UPN; alternate symbols: (C1210H95); part number: CAP_SM-47UF,25V,10,E038014,C1210H95; tolerance: 10
C103 = CAP: User Part Number: UPN; Tolerance: 5; alternate symbols: (C0603); part number: CAP_SM-27PF,50V,5,E062032,C0603; tolerance: 5
C104 C105 = CAP: User Part Number: UPN; Tolerance: 10; alternate symbols: (C0402); part number: CAP_SM-1UF,16V,10,E019219,C0402; tolerance: 10
C118 C119 = CAP: User Part Number: UPN; Tolerance: 10; alternate symbols: (C0603); part number: CAP_SM-4.7UF,35V,10,E039350,C0603; tolerance: 10
C120 = CAP: User Part Number: UPN; Tolerance: 5; alternate symbols: (C0402); part number: CAP_SM-2000PF,25V,5,E019563,C0402; tolerance: 5
C122 = CAP: User Part Number: UPN; Tolerance: 5; alternate symbols: (C0402); part number: CAP_SM-0.027UF,16V,5,E021301,C0402; tolerance: 5
C123 C126 C129 C130 C132 C134 C139 C140 = CAP: User Part Number: UPN; Tolerance: 5; alternate symbols: (C0402); part number: CAP_SM-10PF,50V,5,E007982,C0402; tolerance: 5
C125 = CAP: User Part Number: UPN; Tolerance: 5; alternate symbols: (C0402); part number: CAP_SM-390PF,50V,5,E013656,C0402; tolerance: 5
C137 C138 = CAP: User Part Number: UPN; Tolerance: 10; alternate symbols: (C0402); part number: CAP_SM-1000PF,16V,10,E020949,C0402; tolerance: 10
C141-C144 = CAP: User Part Number: UPN; Tolerance: 10; alternate symbols: (C0603); part number: CAP_SM-2.2UF,10V,10,E015288,C0603; tolerance: 10
CLKIN = CNBNC5P: Tolerance: N/A; User Part Number: UPN; alternate symbols: (CNTYCO78974); part number: CNBNC5P_TH-1-1478979-0,E017193,CNTYCO78974; tolerance: N/A
CNVEN = DIOLED: Tolerance: N/A; User Part Number: UPN; alternate symbols: (LED0603); part number: DIOLED_SM-APT1608LVBC/D,2.65V,N/A,E033357,LED0603; tolerance: N/A
DS1 = DIOLED: Tolerance: N/A; User Part Number: UPN; alternate symbols: (LED0603); part number: DIOLED_SM-APT1608LZGCK,2.65V,N/A,E027397,LED0603; tolerance: N/A
INM INP = CNBNC4P: User Part Number: UPN; Tolerance: N/A; alternate symbols: (CNSMA10G62THK_EDGE); part number: CNBNC4P_SM-142-0701-851,E029168,CNSMA10G62THK_EDGE; tolerance: N/A
IOVDD REF TINM TINP UNK5V_VDD VDD33 VDD_11 VDDLDO VOCM VSS2V5 = CNTP1P: Tolerance: N/A; User Part Number: UPN; alternate symbols: (CNKEY5001TP); part number: CNTP1P_TH-RED,E016323,CNKEY5001TP; tolerance: N/A
JP1 JP2 JP15-JP18 = RESJMPR_3P: User Part Number: UPN; Tolerance: JUMPER; alternate symbols: (3PINJUMPER_0402); part number: RESJMPR_3P_SM-0,E003438,1/10W,JUMPER,3PINJUMPER_0402; tolerance: JUMPER
JP3-JP6 JP19 JP20 = NC3P_JMPR: User Part Number: UPN; Tolerance: N/A; alternate symbols: (3PINJUMPER_0402); part number: NC3P_JMPR_SM-3PIN_JUMPER,E006495,3PINJUMPER_0402; tolerance: N/A
JP7-JP14 JP21-JP25 = RESJMPRSHRT_3P: Tolerance: JUMPER; User Part Number: UPN; alternate symbols: (3PINJUMPER_0603); part number: RESJMPRSHRT_3P_SM-0,E004207,1/10W,JUMPER,3PINJUMPER_0603; tolerance: JUMPER
L1 = IND: User Part Number: UPN; Tolerance: 20; alternate symbols: (LSMSQ118H59_39X118); part number: IND_SM-47UH,20,E054187,LSMSQ118H59_39X118; tolerance: 20
L3 L4 = IND: User Part Number: UPN; Tolerance: 5; alternate symbols: (L0402); part number: IND_SM-100NH,5,E020667,L0402; tolerance: 5
P1 = CN7P: User Part Number: UPN; Tolerance: N/A; alternate symbols: (CNTHMHDR1X7L700W100H433); part number: CN7P_TH-TSW-107-14-G-S,E035158,CNTHMHDR1X7L700W100H433; tolerance: N/A
P2 = CN7P: User Part Number: UPN; Tolerance: N/A; alternate symbols: (CNRCPT1X7H335LD35); part number: CN7P_TH-SSW-107-01-T-S,E016030,CNRCPT1X7H335LD35; tolerance: N/A
P3 = CN160P_CDGH_V2: User Part Number: UPN; Tolerance: N/A; alternate symbols: (CNSAMTECASP-134604-01); part number: CN160P_CDGH_V2_SM-ASP-134604-01,E011383,CNSAMTECASP-134604-01; tolerance: N/A
P4 = CN6P: User Part Number: UPN; Tolerance: N/A; alternate symbols: (CN1X6H335); part number: CN6P_TH-1725698,E019548,CN1X6H335; tolerance: N/A
P5 P6 P9 P10 P12 = CN2P: User Part Number: UPN; Tolerance: N/A; alternate symbols: (CNBERG69157-102); part number: CN2P_TH-69157-102HLF,E000791,CNBERG69157-102; tolerance: N/A
P7 = CN12P_ODD_EVEN: User Part Number: UPN; Tolerance: N/A; alternate symbols: (CNHDR2X6H330); part number: CN12P_ODD_EVEN_TH-TSW-106-07-F-D,E038029,CNHDR2X6H330; tolerance: N/A
P8 = CN4P: User Part Number: UPN; Tolerance: N/A; alternate symbols: (CNPHOENIX1725672); part number: CN4P_TH-1725672,E031182,CNPHOENIX1725672; tolerance: N/A
P11 = CN2P: Tolerance: N/A; User Part Number: UPN; alternate symbols: (CNTH1X2H335); part number: CN2P_TH-1725656,E013431,CNTH1X2H335; tolerance: N/A
R1 R18 R29 R33 R36-R40 R50 R51 R65 R67 R68 R78 R87 R98 R100 R109-R111 R115-R118 R122-R129 R136 R149-R151 = RES: User Part Number: UPN; Tolerance: JUMPER; alternate symbols: (R0402); part number: RES_SM-0,E003438,1/10W,JUMPER,R0402; tolerance: JUMPER; signal model: DEFAULT_RESISTOR_0.001OHM_1_2
R2 R3 = RES: User Part Number: UPN; Tolerance: 1; alternate symbols: (R0603); part number: RES_SM-49.9,E003673,1/10W,1,R0603; tolerance: 1; signal model: DEFAULT_RESISTOR_49.900000OHM_1_2
R4 R6 R17 R30 R52 R57 R66 R70 R76 R90 R106 R114 R146 R147 = RES: User Part Number: UPN; Tolerance: N/A; alternate symbols: (R0603); part number: RES_SM-0,E005803,N/A,N/A,R0603; tolerance: N/A; signal model: DEFAULT_RESISTOR_0.001OHM_1_2
R5 R7 = RES: User Part Number: UPN; Tolerance: 1; alternate symbols: (R0603); part number: RES_SM-499,E003667,1/10W,1,R0603; tolerance: 1; signal model: DEFAULT_RESISTOR_499.000000OHM_1_2
R8 R9 = RES: User Part Number: UPN; Tolerance: 1; alternate symbols: (R0603); part number: RES_SM-499,E003667,1/10W,1,R0603; tolerance: 1
R10 R11 R14 R15 = RES: User Part Number: UPN; Tolerance: 0.1; alternate symbols: (R0603); part number: RES_SM-300,E039483,1/10W,0.1,R0603; tolerance: 0.1
R12 R13 = RES: User Part Number: UPN; Tolerance: JUMPER; alternate symbols: (R0603); part number: RES_SM-0,E007502,1/10W,JUMPER,R0603; tolerance: JUMPER
R16 R43-R45 R47 = RES: User Part Number: UPN; Tolerance: 1; alternate symbols: (R0402); part number: RES_SM-10K,E003751,1/10W,1,R0402; tolerance: 1
R19 R20 R35 = RES: User Part Number: UPN; Tolerance: 5; alternate symbols: (R0402); part number: RES_SM-100K,E003464,1/10W,5,R0402; tolerance: 5
R21-R23 R34 R79-R84 R91-R94 R132 = RES: User Part Number: UPN; Tolerance: N/A; alternate symbols: (R0603); part number: RES_SM-0,E005803,N/A,N/A,R0603; tolerance: N/A
R24 = RES: Tolerance: JUMPER; User Part Number: UPN; alternate symbols: (R0201); part number: RES_SM-0,E004015,1/20W,JUMPER,R0201; tolerance: JUMPER; signal model: DEFAULT_RESISTOR_0.001OHM_1_2
R26-R28 R113 R152 = RES: User Part Number: UPN; Tolerance: JUMPER; alternate symbols: (R0603); part number: RES_SM-0,E027148,1/4W,JUMPER,R0603; tolerance: JUMPER; signal model: DEFAULT_RESISTOR_0.001OHM_1_2
R31 R89 = RES: User Part Number: UPN; Tolerance: 1; alternate symbols: (R0603); part number: RES_SM-68,E004250,1/16W,1,R0603; tolerance: 1; signal model: DEFAULT_RESISTOR_68.000000OHM_1_2
R32 R88 = RES: User Part Number: UPN; Tolerance: 0.1; alternate symbols: (R0603); part number: RES_SM-20,E003972,1/8W,0.1,R0603; tolerance: 0.1; signal model: DEFAULT_RESISTOR_20.000000OHM_1_2
R41 = RES: User Part Number: UPN; Tolerance: 1; alternate symbols: (R0402); part number: RES_SM-35.7K,E021987,1/10W,1,R0402; tolerance: 1; signal model: DEFAULT_RESISTOR_35700OHM_1_2
R42 R86 R99 R101 R148 = RES: User Part Number: UPN; Tolerance: 1; alternate symbols: (R0402); part number: RES_SM-10K,E003751,1/10W,1,R0402; tolerance: 1; signal model: DEFAULT_RESISTOR_10000OHM_1_2
R46 = RES: User Part Number: UPN; Tolerance: 1; alternate symbols: (R0402); part number: RES_SM-1.5K,E003782,1/10W,1,R0402; tolerance: 1
R48 R49 = RES: User Part Number: UPN; Tolerance: 1; alternate symbols: (R0402); part number: RES_SM-10,E003768,1/10W,1,R0402; tolerance: 1; signal model: DEFAULT_RESISTOR_10.000000OHM_1_2
R53-R56 = RES: User Part Number: UPN; Tolerance: 5; alternate symbols: (R0402); part number: RES_SM-100K,E003464,1/10W,5,R0402; tolerance: 5; signal model: DEFAULT_RESISTOR_100000OHM_1_2
R58 R59 = RES: User Part Number: UPN; Tolerance: 0.1; alternate symbols: (R0603); part number: RES_SM-25,E007185,1/8W,0.1,R0603; tolerance: 0.1; signal model: DEFAULT_RESISTOR_25.000000OHM_1_2
R60 R85 = RES: User Part Number: UPN; Tolerance: 5; alternate symbols: (R0402); part number: RES_SM-1.1K,E003458,1/10W,5,R0402; tolerance: 5; signal model: DEFAULT_RESISTOR_1100OHM_1_2
R61 R71-R75 = RES: User Part Number: UPN; Tolerance: 1; alternate symbols: (R0402); part number: RES_SM-100K,E003796,1/10W,1,R0402; tolerance: 1; signal model: DEFAULT_RESISTOR_100000OHM_1_2
R62 R69 = RES: User Part Number: UPN; Tolerance: 5; alternate symbols: (R0402); part number: RES_SM-100,E003443,1/10W,5,R0402; tolerance: 5; signal model: DEFAULT_RESISTOR_100.000000OHM_1_2
R63 R64 = RES: User Part Number: UPN; Tolerance: 1; alternate symbols: (R0402); part number: RES_SM-49.9,E003750,1/10W,1,R0402; tolerance: 1; signal model: DEFAULT_RESISTOR_49.900000OHM_1_2
R77 R133 = RES: Tolerance: 1; User Part Number: UPN; alternate symbols: (R0201); part number: RES_SM-100K,E007919,1/20W,1,R0201; tolerance: 1; signal model: DEFAULT_RESISTOR_100000OHM_1_2
R95 = RES: User Part Number: UPN; Tolerance: 1; alternate symbols: (R0603); part number: RES_SM-33K,E028267,1/10W,1,R0603; tolerance: 1; signal model: DEFAULT_RESISTOR_33000OHM_1_2
R96 = RES: User Part Number: UPN; Tolerance: 1; alternate symbols: (R0603); part number: RES_SM-20K,E017927,1/10W,1,R0603; tolerance: 1; signal model: DEFAULT_RESISTOR_20000OHM_1_2
R97 R107 = RES: User Part Number: UPN; Tolerance: 0.1; alternate symbols: (R0603); part number: RES_SM-11K,E021508,1/10W,0.1,R0603; tolerance: 0.1; signal model: DEFAULT_RESISTOR_11000OHM_1_2
R102 R103 = RES: User Part Number: UPN; Tolerance: 0.1; alternate symbols: (R0603); part number: RES_SM-56,E032709,1/10W,0.1,R0603; tolerance: 0.1
R104 R105 = RES: User Part Number: UPN; Tolerance: 5; alternate symbols: (R0603); part number: RES_SM-5.6,E003856,1/10W,5,R0603; tolerance: 5; signal model: DEFAULT_RESISTOR_5.600000OHM_1_2
R108 R112 R130 R131 = RES: User Part Number: UPN; Tolerance: 5; alternate symbols: (R0603); part number: RES_SM-3K,E003850,1/10W,5,R0603; tolerance: 5; signal model: DEFAULT_RESISTOR_3000OHM_1_2
R119 = RES: User Part Number: UPN; Tolerance: 1; alternate symbols: (R0402); part number: RES_SM-316,E022003,1/10W,1,R0402; tolerance: 1; signal model: DEFAULT_RESISTOR_316.000000OHM_1_2
R120 = RES: User Part Number: UPN; Tolerance: 1; alternate symbols: (R0402); part number: RES_SM-845,E007511,1/10W,1,R0402; tolerance: 1; signal model: DEFAULT_RESISTOR_845.000000OHM_1_2
R121 = RES: User Part Number: UPN; Tolerance: 0.1; alternate symbols: (R0402); part number: RES_SM-5.1K,E010267,1/16W,0.1,R0402; tolerance: 0.1; signal model: DEFAULT_RESISTOR_5100OHM_1_2
R134 = RES: User Part Number: UPN; Tolerance: 0.1; alternate symbols: (R0603); part number: RES_SM-50K,E020895,0.15W,0.1,R0603; tolerance: 0.1; signal model: DEFAULT_RESISTOR_50000OHM_1_2
R135 = RES: User Part Number: UPN; Tolerance: 1; alternate symbols: (R0603); part number: RES_SM-500,E012854,1/10W,1,R0603; tolerance: 1; signal model: DEFAULT_RESISTOR_500.000000OHM_1_2
R137 = RES: User Part Number: UPN; Tolerance: 1; alternate symbols: (R0603); part number: RES_SM-18.2K,E011126,1/10W,1,R0603; tolerance: 1; signal model: DEFAULT_RESISTOR_18200OHM_1_2
R138 = RES: User Part Number: UPN; Tolerance: 1; alternate symbols: (R0603); part number: RES_SM-187K,E032773,1/10W,1,R0603; tolerance: 1; signal model: DEFAULT_RESISTOR_187000OHM_1_2
R139 = RES: User Part Number: UPN; Tolerance: 1; alternate symbols: (R0603); part number: RES_SM-1MEG,E003682,1/10W,1,R0603; tolerance: 1; signal model: DEFAULT_RESISTOR_1e+06OHM_1_2
RTCLK RTCNV = RES: User Part Number: UPN; Tolerance: 1; alternate symbols: (R0402); part number: RES_SM-100,E003760,1/16W,1,R0402; tolerance: 1; signal model: DEFAULT_RESISTOR_100.000000OHM_1_2
S1 = SWSPST8P: Tolerance: N/A; User Part Number: UPN; alternate symbols: (SWSML246W228H104); part number: SWSPST8P_SM-218-4LPST,E042353,SWSML246W228H104; tolerance: N/A
T1 = XFMRETC1: Tolerance: N/A; User Part Number: UPN; alternate symbols: (ETC1); part number: XFMRETC1_SM-MABA-007159-000000,E006308,ETC1; tolerance: N/A
TP1-TP4 = CNTP1P: Tolerance: N/A; User Part Number: UPN; alternate symbols: (CNKEY5001TP); part number: CNTP1P_TH-BLK,E005347,CNKEY5001TP; tolerance: N/A
U1 U2 = ADLT6236: User Part Number: UPN; Tolerance: N/A; alternate symbols: (TSOT23_6); part number: ADLT6236_SM-LT6236HS6#TRMPBF,E045557,TSOT23_6; tolerance: N/A
U3 = ADA4945_1: User Part Number: UPN; Tolerance: N/A; alternate symbols: (QFN16_3X3_PAD1_6X1_6); part number: ADA4945_1_SM-ADA4945-1ACPZ-R7,E028779,QFN16_3X3_PAD1_6X1_6; tolerance: N/A
U4-U7 U9 U11-U17 = 74AVC1T45: Tolerance: N/A; User Part Number: UPN; alternate symbols: (SC70-6); part number: 74AVC1T45_SM-SN74AVC1T45DCKR,E010914,SC70-6; tolerance: N/A
U8 = AD4080: User Part Number: UPN; Tolerance: N/A; alternate symbols: (BGA49_5X5); part number: AD4080_SM-AD4080,E055563,BGA49_5X5; tolerance: N/A
U18 = ICM24CXX: Tolerance: N/A; User Part Number: UPN; alternate symbols: (SO8); part number: ICM24CXX_SM-M24C02-RMN6TP,E018349,SO8; tolerance: N/A
U19 = ADP7182_V3: User Part Number: UPN; Tolerance: N/A; alternate symbols: (TSOT-5); part number: ADP7182_V3_SM-ADP7182AUJZ-2.5,E021384,TSOT-5; tolerance: N/A
U20 = AD9508: User Part Number: UPN; Tolerance: N/A; alternate symbols: (QFN24_4X4_PAD2_3X2_3); part number: AD9508_SM-AD9508BCPZ,E015653,QFN24_4X4_PAD2_3X2_3; tolerance: N/A
U21 U33-U35 U37 = LINLT3045: Tolerance: N/A; User Part Number: UPN; alternate symbols: (MSOP12_PAD2_845X1_651); part number: LINLT3045_SM-LT3045EMSE#PBF,E029908,MSOP12_PAD2_845X1_651; tolerance: N/A
U23 U24 U28 = CMOSTC7S08F: Tolerance: N/A; User Part Number: UPN; alternate symbols: (SC70-5-2); part number: CMOSTC7S08F_SM-TC7S08FU,LF,E057741,SC70-5_A; tolerance: N/A
U25 = LINLTC6655: Tolerance: N/A; User Part Number: UPN; alternate symbols: (MSOP8); part number: LINLTC6655_SM-LTC6655BHMS8-3#PBF,E030837,MSOP8; tolerance: N/A
U26 U27 = 741G00: Tolerance: N/A; User Part Number: UPN; alternate symbols: (SC70-5-2); part number: 741G00_SM-SN74LVC1G00DCKT,E022723,SC70-5; tolerance: N/A
U29 = CMOSNC7SZ125: User Part Number: UPN; Tolerance: N/A; alternate symbols: (SOT23-M12); part number: CMOSNC7SZ125_SM-NC7SZ125M5X,E006818,SOT23-M12; tolerance: N/A
U30 = ADF435X: User Part Number: UPN; Tolerance: N/A; alternate symbols: (QFN32_5X5_PAD3_1X3_1); part number: ADF435X_SM-ADF4350BCPZ,E010559,QFN32_5X5_PAD3_1X3_1; tolerance: N/A
U31 U32 = ADP7118_V2: User Part Number: UPN; Tolerance: N/A; alternate symbols: (TSOT-5); part number: ADP7118_V2_SM-ADP7118AUJZ-3.3,E021874,TSOT-5; tolerance: N/A
U36 = LINLT6657: Tolerance: N/A; User Part Number: UPN; alternate symbols: (MSOP8); part number: LINLT6657_SM-LT6657BHMS8-3#PBF,E049786,MSOP8; tolerance: N/A
U38 = ADLT8604: User Part Number: UPN; Tolerance: N/A; alternate symbols: (QFN12_2X2_PAD0_7X0_7); part number: ADLT8604_SM-LT8604CAV#TRMPBF,E055399,QFN12_2X2_PAD0_7X0_7; tolerance: N/A
U39 = ADA4897_1: User Part Number: UPN; Tolerance: N/A; alternate symbols: (SOT23_6-2); part number: ADA4897_1_SM-ADA4897-1ARJZ,E018786,SOT23_6-2; tolerance: N/A
Y1 = XTALOSC4P_V2: Tolerance: 2PPM; User Part Number: UPN; alternate symbols: (YSML79W63H31_A); part number: XTALOSC4P_V2_SM-25MEGHZ,E058656,YSML79W63H31_A; tolerance: 2PPM

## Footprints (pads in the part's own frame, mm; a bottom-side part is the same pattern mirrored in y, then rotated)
3PINJUMPER_0402
  rect 0.737x0.635 smd: 1(0,1.001)
  rect 0.737x0.737 smd: 2(0,0)
  rect 0.635x0.737 smd: 3(-1.001,0)
3PINJUMPER_0603
  rect 1.295x1.397 smd: 1(-0.953,0)
  rect 1.397x1.397 smd: 2(0.953,0)
  rect 1.397x1.295 smd: 3(0.953,1.905)
BGA49_5X5
  round 0.305 smd: A1(-1.95,-1.95) A2(-1.95,-1.3) A3(-1.95,-0.65) A4(-1.95,0) A5(-1.95,0.65) A6(-1.95,1.3) A7(-1.95,1.95) B1(-1.3,-1.95) B2(-1.3,-1.3) B3(-1.3,-0.65) B4(-1.3,0) B5(-1.3,0.65) B6(-1.3,1.3) B7(-1.3,1.95) C1(-0.65,-1.95) C2(-0.65,-1.3) C3(-0.65,-0.65) C4(-0.65,0) C5(-0.65,0.65) C6(-0.65,1.3) C7(-0.65,1.95) D1(0,-1.95) D2(0,-1.3) D3(0,-0.65) D4(0,0) D5(0,0.65) D6(0,1.3) D7(0,1.95) E1(0.65,-1.95) E2(0.65,-1.3) E3(0.65,-0.65) E4(0.65,0) E5(0.65,0.65) E6(0.65,1.3) E7(0.65,1.95) F1(1.3,-1.95) F2(1.3,-1.3) F3(1.3,-0.65) F4(1.3,0) F5(1.3,0.65) F6(1.3,1.3) F7(1.3,1.95) G1(1.95,-1.95) G2(1.95,-1.3) G3(1.95,-0.65) G4(1.95,0) G5(1.95,0.65) G6(1.95,1.3) G7(1.95,1.95)
C0201
  rect 0.305x0.406 smd: 1(-0.318,0) 2(0.318,0)
C0402
  rect 0.584x0.66 smd: 1(-0.5,0) 2(0.5,0)
C0402H22
  rect 0.559x0.508 smd: 1(-0.479,0) 2(0.479,0)
C0603
  rect 0.94x0.991 smd: 1(-0.8,0) 2(0.8,0)
C0603_0805
  rect 1.143x1.448 smd: 1(-0.9,0) 2(0.9,0)
C0805
  rect 1.143x1.448 smd: 1(-0.9,0) 2(0.9,0)
C0805H60
  rect 1.295x1.6 smd: 1(-0.953,0) 2(0.953,0)
C1206H71
  rect 1.6x2.007 smd: 1(-1.397,0) 2(1.397,0)
C1210H95
  rect 1.575x2.692 smd: 1(-1.397,0) 2(1.397,0)
C1210H106
  rect 1.092x2.057 smd: 1(-1.646,0) 2(1.646,0)
CN1X6H335
  rect 1.651x1.651 hole 1.143: 1(0,0)
  round 1.651 hole 1.143: 2(2.54,0) 3(5.08,0) 4(7.62,0) 5(10.16,0) 6(12.7,0)
CNBERG69157-102
  rect 1.524x1.524 hole 1.016: 1(0,0)
  round 1.524 hole 1.016: 2(2.54,0)
CNHDR2X6H330
  rect 1.651x1.651 hole 1.143: 1(0,0)
  round 1.651 hole 1.143: 2(0,2.54) 3(2.54,0) 4(2.54,2.54) 5(5.08,0) 6(5.08,2.54) 7(7.62,0) 8(7.62,2.54) 9(10.16,0) 10(10.16,2.54) 11(12.7,0) 12(12.7,2.54)
CNKEY5001TP
  round 1.524 hole 1.016: 1(0,0)
CNPHOENIX1725672
  rect 1.778x1.778 hole 1.27: 1(0,0)
  round 1.778 hole 1.27: 2(2.54,0) 3(5.08,0) 4(7.62,0)
CNRCPT1X7H335LD35
  rect 1.651x1.651 hole 1.143: 1(0,0)
  round 1.651 hole 1.143: 2(2.54,0) 3(5.08,0) 4(7.62,0) 5(10.16,0) 6(12.7,0) 7(15.24,0)
CNSAMTECASP-134604-01
  round 2.54 hole 1.27 unplated: (-27.191,0) (27.191,3.048)
  round 0.635 smd: C1(-24.765,-3.175) C2(-23.495,-3.175) C3(-22.225,-3.175) C4(-20.955,-3.175) C5(-19.685,-3.175) C6(-18.415,-3.175) C7(-17.145,-3.175) C8(-15.875,-3.175) C9(-14.605,-3.175) C10(-13.335,-3.175) C11(-12.065,-3.175) C12(-10.795,-3.175) C13(-9.525,-3.175) C14(-8.255,-3.175) C15(-6.985,-3.175) C16(-5.715,-3.175) C17(-4.445,-3.175) C18(-3.175,-3.175) C19(-1.905,-3.175) C20(-0.635,-3.175) C21(0.635,-3.175) C22(1.905,-3.175) C23(3.175,-3.175) C24(4.445,-3.175) C25(5.715,-3.175) C26(6.985,-3.175) C27(8.255,-3.175) C28(9.525,-3.175) C29(10.795,-3.175) C30(12.065,-3.175) C31(13.335,-3.175) C32(14.605,-3.175) C33(15.875,-3.175) C34(17.145,-3.175) C35(18.415,-3.175) C36(19.685,-3.175) C37(20.955,-3.175) C38(22.225,-3.175) C39(23.495,-3.175) C40(24.765,-3.175) D1(-24.765,-1.905) D2(-23.495,-1.905) D3(-22.225,-1.905) D4(-20.955,-1.905) D5(-19.685,-1.905) D6(-18.415,-1.905) D7(-17.145,-1.905) D8(-15.875,-1.905) D9(-14.605,-1.905) D10(-13.335,-1.905) D11(-12.065,-1.905) D12(-10.795,-1.905) D13(-9.525,-1.905) D14(-8.255,-1.905) D15(-6.985,-1.905) D16(-5.715,-1.905) D17(-4.445,-1.905) D18(-3.175,-1.905) D19(-1.905,-1.905) D20(-0.635,-1.905) D21(0.635,-1.905) D22(1.905,-1.905) D23(3.175,-1.905) D24(4.445,-1.905) D25(5.715,-1.905) D26(6.985,-1.905) D27(8.255,-1.905) D28(9.525,-1.905) D29(10.795,-1.905) D30(12.065,-1.905) D31(13.335,-1.905) D32(14.605,-1.905) D33(15.875,-1.905) D34(17.145,-1.905) D35(18.415,-1.905) D36(19.685,-1.905) D37(20.955,-1.905) D38(22.225,-1.905) D39(23.495,-1.905) D40(24.765,-1.905) G1(-24.765,1.905) G2(-23.495,1.905) G3(-22.225,1.905) G4(-20.955,1.905) G5(-19.685,1.905) G6(-18.415,1.905) G7(-17.145,1.905) G8(-15.875,1.905) G9(-14.605,1.905) G10(-13.335,1.905) G11(-12.065,1.905) G12(-10.795,1.905) G13(-9.525,1.905) G14(-8.255,1.905) G15(-6.985,1.905) G16(-5.715,1.905) G17(-4.445,1.905) G18(-3.175,1.905) G19(-1.905,1.905) G20(-0.635,1.905) G21(0.635,1.905) G22(1.905,1.905) G23(3.175,1.905) G24(4.445,1.905) G25(5.715,1.905) G26(6.985,1.905) G27(8.255,1.905) G28(9.525,1.905) G29(10.795,1.905) G30(12.065,1.905) G31(13.335,1.905) G32(14.605,1.905) G33(15.875,1.905) G34(17.145,1.905) G35(18.415,1.905) G36(19.685,1.905) G37(20.955,1.905) G38(22.225,1.905) G39(23.495,1.905) G40(24.765,1.905) H1(-24.765,3.175) H2(-23.495,3.175) H3(-22.225,3.175) H4(-20.955,3.175) H5(-19.685,3.175) H6(-18.415,3.175) H7(-17.145,3.175) H8(-15.875,3.175) H9(-14.605,3.175) H10(-13.335,3.175) H11(-12.065,3.175) H12(-10.795,3.175) H13(-9.525,3.175) H14(-8.255,3.175) H15(-6.985,3.175) H16(-5.715,3.175) H17(-4.445,3.175) H18(-3.175,3.175) H19(-1.905,3.175) H20(-0.635,3.175) H21(0.635,3.175) H22(1.905,3.175) H23(3.175,3.175) H24(4.445,3.175) H25(5.715,3.175) H26(6.985,3.175) H27(8.255,3.175) H28(9.525,3.175) H29(10.795,3.175) H30(12.065,3.175) H31(13.335,3.175) H32(14.605,3.175) H33(15.875,3.175) H34(17.145,3.175) H35(18.415,3.175) H36(19.685,3.175) H37(20.955,3.175) H38(22.225,3.175) H39(23.495,3.175) H40(24.765,3.175)
CNSMA10G62THK_EDGE
  custom 0.584x0.584 smd: 1(-1.206,0)
  custom 0.73x0.73 smd: 2(-2.667,-3.696) 3(-2.667,3.708)
  rect 5.334x10.414 smd: 4(-2.743,0)
CNTH1X2H335
  round 1.448 hole 1.194 unplated: (0,-2.54) (2.54,-2.54)
  rect 1.651x1.651 hole 1.143: 1(0,0)
  round 1.651 hole 1.143: 2(2.54,0)
CNTHMHDR1X7L700W100H433
  rect 1.651x1.651 hole 1.143: 1(-7.62,0)
  round 1.651 hole 1.143: 2(-5.08,0) 3(-2.54,0) 4(0,0) 5(2.54,0) 6(5.08,0) 7(7.62,0)
CNTYCO78974
  round 1.905 hole 1.397: 1(0,0)
  round 2.032 hole 1.524: 2(-2.55,2.55) 3(2.55,2.55) 4(2.55,-2.55) 5(-2.55,-2.55)
ETC1
  rect 0.762x1.397 smd: 1(-1.27,1.714) 2(0,1.714) 3(1.27,1.714) 4(1.27,-1.714) 5(-1.27,-1.714)
L0402
  rect 0.584x0.711 smd: 1(-0.475,0) 2(0.475,0)
LED0603
  rect 0.965x0.762 smd: A(0.8,0) C(-0.8,0)
LSMSQ118H59_39X118
  rect 0.991x2.997 smd: 1(-0.995,0) 2(0.995,0)
MSOP8
  rect 0.305x1.321 smd: 1(-0.975,-2.3) 2(-0.325,-2.3) 3(0.325,-2.3) 4(0.975,-2.3) 5(0.975,2.3) 6(0.325,2.3) 7(-0.325,2.3) 8(-0.975,2.3)
MSOP12_PAD2_845X1_651
  rect 0.432x0.889 smd: 1(-1.625,-2.107) 2(-0.975,-2.107) 3(-0.325,-2.107) 4(0.325,-2.107) 5(0.975,-2.107) 6(1.625,-2.107) 7(1.625,2.107) 8(0.975,2.107) 9(0.325,2.107) 10(-0.325,2.107) 11(-0.975,2.107) 12(-1.625,2.107)
  rect 2.845x1.651 smd: PAD(0,0)
QFN12_2X2_PAD0_7X0_7
  oval 0.279x0.711 smd: 1(-0.75,-0.906) 2(-0.25,-0.906) 3(0.25,-0.906) 4(0.75,-0.906) 7(0.75,0.906) 8(0.25,0.906) 9(-0.25,0.906) 10(-0.75,0.906)
  oval 0.711x0.279 smd: 5(0.906,-0.25) 6(0.906,0.25) 11(-0.906,0.25) 12(-0.906,-0.25)
  rect 0.711x0.711 smd: PAD(0,0)
QFN16_3X3_PAD1_6X1_6
  oval 0.305x0.889 smd: 1(-0.75,-1.5) 2(-0.25,-1.5) 3(0.25,-1.5) 4(0.75,-1.5) 9(0.75,1.5) 10(0.25,1.5) 11(-0.25,1.5) 12(-0.75,1.5)
  oval 0.889x0.305 smd: 5(1.5,-0.75) 6(1.5,-0.25) 7(1.5,0.25) 8(1.5,0.75) 13(-1.5,0.75) 14(-1.5,0.25) 15(-1.5,-0.25) 16(-1.5,-0.75)
  rect 1.6x1.6 smd: PAD(0,0)
QFN24_4X4_PAD2_3X2_3
  oval 0.305x0.991 smd: 1(-1.25,-2) 2(-0.75,-2) 3(-0.25,-2) 4(0.25,-2) 5(0.75,-2) 6(1.25,-2) 13(1.25,2) 14(0.75,2) 15(0.25,2) 16(-0.25,2) 17(-0.75,2) 18(-1.25,2)
  oval 0.991x0.305 smd: 7(2,-1.25) 8(2,-0.75) 9(2,-0.25) 10(2,0.25) 11(2,0.75) 12(2,1.25) 19(-2,1.25) 20(-2,0.75) 21(-2,0.25) 22(-2,-0.25) 23(-2,-0.75) 24(-2,-1.25)
  rect 2.311x2.311 smd: PAD(0,0)
QFN32_5X5_PAD3_1X3_1
  oval 0.305x0.889 smd: 1(-1.75,-2.45) 2(-1.25,-2.45) 3(-0.75,-2.45) 4(-0.25,-2.45) 5(0.25,-2.45) 6(0.75,-2.45) 7(1.25,-2.45) 8(1.75,-2.45) 17(1.75,2.45) 18(1.25,2.45) 19(0.75,2.45) 20(0.25,2.45) 21(-0.25,2.45) 22(-0.75,2.45) 23(-1.25,2.45) 24(-1.75,2.45)
  oval 0.889x0.305 smd: 9(2.45,-1.75) 10(2.45,-1.25) 11(2.45,-0.75) 12(2.45,-0.25) 13(2.45,0.25) 14(2.45,0.75) 15(2.45,1.25) 16(2.45,1.75) 25(-2.45,1.75) 26(-2.45,1.25) 27(-2.45,0.75) 28(-2.45,0.25) 29(-2.45,-0.25) 30(-2.45,-0.75) 31(-2.45,-1.25) 32(-2.45,-1.75)
  rect 3.099x3.099 smd: PAD(0,0)
R0201
  rect 0.305x0.406 smd: 1(-0.318,0) 2(0.318,0)
R0402
  rect 0.635x0.737 smd: 1(-0.5,0) 2(0.5,0)
R0603
  rect 0.787x0.991 smd: 1(-0.85,0) 2(0.85,0)
SC70-5
  rect 0.406x0.508 smd: 1(-0.65,-0.95) 2(0,-0.95) 3(0.65,-0.95) 4(0.65,0.95) 5(-0.65,0.95)
SC70-5_A
  rect 0.406x0.508 smd: 1(-0.65,-0.95) 2(0,-0.95) 3(0.65,-0.95) 4(0.65,0.95) 5(-0.65,0.95)
SC70-6
  rect 0.406x0.508 smd: 1(-0.65,-0.95) 2(0,-0.95) 3(0.65,-0.95) 4(0.65,0.95) 5(0,0.95) 6(-0.65,0.95)
SO8
  rect 0.61x2.184 smd: 1(-1.905,-2.54) 2(-0.635,-2.54) 3(0.635,-2.54) 4(1.905,-2.54) 5(1.905,2.54) 6(0.635,2.54) 7(-0.635,2.54) 8(-1.905,2.54)
SO8NB-3-PAD
  rect 0.635x1.422 smd: 1(-1.905,-2.819) 2(-0.635,-2.819) 3(0.635,-2.819) 4(1.905,-2.819) 5(1.905,2.819) 6(0.635,2.819) 7(-0.635,2.819) 8(-1.905,2.819)
  rect 2.794x2.413 smd: PAD(0,0)
SOT23-M12
  rect 0.711x1.27 smd: 1(-0.953,-1.27) 2(0,-1.27) 3(0.953,-1.27) 4(0.953,1.27) 5(-0.953,1.27)
SOT23_6-2
  rect 0.711x0.991 smd: 1(-0.95,-1.2) 2(0,-1.2) 3(0.95,-1.2) 4(0.95,1.2) 5(0,1.2) 6(-0.95,1.2)
SWSML246W228H104
  rect 0.762x1.27 smd: 1A(-1.905,-3.81) 1B(-1.905,3.81) 2A(-0.635,-3.81) 2B(-0.635,3.81) 3A(0.635,-3.81) 3B(0.635,3.81) 4A(1.905,-3.81) 4B(1.905,3.81)
